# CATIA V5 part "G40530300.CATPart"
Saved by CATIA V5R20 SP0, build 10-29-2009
Part number: G40530300
Revision: 5
Definition: design
Nomenclature: G40530300
Source: made
Description: NOT SPECIFIED
Bounding box of the stored display mesh (mm): x -150 to 150, y -12.5 to 12.5, z -30 to 0
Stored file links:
  C:\Users\Raffaele\Desktop\3D X SITO CF\BOLEX\29-GUIDE STRIP REF 405\G40530300.CATPart
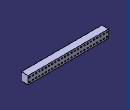
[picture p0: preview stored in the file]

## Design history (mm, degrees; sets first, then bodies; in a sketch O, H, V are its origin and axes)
Body1 "MANIFOLD_SOLID_BREP #7846" (main body)
  Solid1: solid without history
Body2 "MANIFOLD_SOLID_BREP #7984"
  Solid2: solid without history
Body3 "MANIFOLD_SOLID_BREP #8096"
  Solid3: solid without history
Body4 "MANIFOLD_SOLID_BREP #8208"
  Solid4: solid without history
Body5 "MANIFOLD_SOLID_BREP #8320"
  Solid5: solid without history
Body6 "MANIFOLD_SOLID_BREP #8432"
  Solid6: solid without history
Body7 "MANIFOLD_SOLID_BREP #8544"
  Solid7: solid without history
Body8 "MANIFOLD_SOLID_BREP #8656"
  Solid8: solid without history
Body9 "MANIFOLD_SOLID_BREP #8768"
  Solid9: solid without history
Body10 "MANIFOLD_SOLID_BREP #8880"
  Solid10: solid without history
Body11 "MANIFOLD_SOLID_BREP #8992"
  Solid11: solid without history
Body12 "MANIFOLD_SOLID_BREP #9104"
  Solid12: solid without history
Body13 "MANIFOLD_SOLID_BREP #9242"
  Solid13: solid without history
Body14 "MANIFOLD_SOLID_BREP #9380"
  Solid14: solid without history
Body15 "MANIFOLD_SOLID_BREP #9518"
  Solid15: solid without history
Body16 "MANIFOLD_SOLID_BREP #9656"
  Solid16: solid without history
Body17 "MANIFOLD_SOLID_BREP #9794"
  Solid17: solid without history
Body18 "MANIFOLD_SOLID_BREP #9932"
  Solid18: solid without history
Body19 "MANIFOLD_SOLID_BREP #10070"
  Solid19: solid without history
Body20 "MANIFOLD_SOLID_BREP #10208"
  Solid20: solid without history
Body21 "MANIFOLD_SOLID_BREP #10320"
  Solid21: solid without history
Body22 "MANIFOLD_SOLID_BREP #10432"
  Solid22: solid without history
Body23 "MANIFOLD_SOLID_BREP #10544"
  Solid23: solid without history
Body24 "MANIFOLD_SOLID_BREP #10656"
  Solid24: solid without history
Body25 "MANIFOLD_SOLID_BREP #10768"
  Solid25: solid without history
Body26 "MANIFOLD_SOLID_BREP #10880"
  Solid26: solid without history
Body27 "MANIFOLD_SOLID_BREP #10992"
  Solid27: solid without history
Body28 "MANIFOLD_SOLID_BREP #11104"
  Solid28: solid without history
Body29 "MANIFOLD_SOLID_BREP #11216"
  Solid29: solid without history
Body30 "MANIFOLD_SOLID_BREP #11328"
  Solid30: solid without history
Body31 "MANIFOLD_SOLID_BREP #11466"
  Solid31: solid without history
Body32 "MANIFOLD_SOLID_BREP #11604"
  Solid32: solid without history
Body33 "MANIFOLD_SOLID_BREP #11742"
  Solid33: solid without history
Body34 "MANIFOLD_SOLID_BREP #11880"
  Solid34: solid without history
Body35 "MANIFOLD_SOLID_BREP #12018"
  Solid35: solid without history
Body36 "MANIFOLD_SOLID_BREP #12156"
  Solid36: solid without history
Body37 "MANIFOLD_SOLID_BREP #12268"
  Solid37: solid without history
Body38 "MANIFOLD_SOLID_BREP #12380"
  Solid38: solid without history
Body39 "MANIFOLD_SOLID_BREP #12492"
  Solid39: solid without history
Body40 "MANIFOLD_SOLID_BREP #12604"
  Solid40: solid without history
Body41 "MANIFOLD_SOLID_BREP #12716"
  Solid41: solid without history
Body42 "MANIFOLD_SOLID_BREP #12828"
  Solid42: solid without history
Body43 "MANIFOLD_SOLID_BREP #12940"
  Solid43: solid without history
Body44 "MANIFOLD_SOLID_BREP #13052"
  Solid44: solid without history
Body45 "MANIFOLD_SOLID_BREP #13164"
  Solid45: solid without history
Body46 "MANIFOLD_SOLID_BREP #13276"
  Solid46: solid without history
Body47 "MANIFOLD_SOLID_BREP #13388"
  Solid47: solid without history
Body48 "MANIFOLD_SOLID_BREP #13500"
  Solid48: solid without history
Body49 "MANIFOLD_SOLID_BREP #13612"
  Solid49: solid without history
Body50 "MANIFOLD_SOLID_BREP #13724"
  Solid50: solid without history
Body51 "MANIFOLD_SOLID_BREP #13836"
  Solid51: solid without history
Body52 "MANIFOLD_SOLID_BREP #13948"
  Solid52: solid without history
Body53 "MANIFOLD_SOLID_BREP #14060"
  Solid53: solid without history
Body54 "MANIFOLD_SOLID_BREP #14172"
  Solid54: solid without history
Body55 "MANIFOLD_SOLID_BREP #14284"
  Solid55: solid without history
Body56 "MANIFOLD_SOLID_BREP #14396"
  Solid56: solid without history
Body57 "MANIFOLD_SOLID_BREP #14508"
  Solid57: solid without history
Body58 "MANIFOLD_SOLID_BREP #14646"
  Solid58: solid without history
Body59 "MANIFOLD_SOLID_BREP #14784"
  Solid59: solid without history
Body60 "MANIFOLD_SOLID_BREP #14922"
  Solid60: solid without history
Body61 "MANIFOLD_SOLID_BREP #15060"
  Solid61: solid without history
Body62 "MANIFOLD_SOLID_BREP #15198"
  Solid62: solid without history
Body63 "MANIFOLD_SOLID_BREP #15336"
  Solid63: solid without history
Body64 "MANIFOLD_SOLID_BREP #15474"
  Solid64: solid without history
Body65 "MANIFOLD_SOLID_BREP #15612"
  Solid65: solid without history
Body66 "MANIFOLD_SOLID_BREP #15750"
  Solid66: solid without history
Body67 "MANIFOLD_SOLID_BREP #15862"
  Solid67: solid without history
Body68 "MANIFOLD_SOLID_BREP #15974"
  Solid68: solid without history
Body69 "MANIFOLD_SOLID_BREP #16086"
  Solid69: solid without history
Body70 "MANIFOLD_SOLID_BREP #16198"
  Solid70: solid without history
Body71 "MANIFOLD_SOLID_BREP #16310"
  Solid71: solid without history
Body72 "MANIFOLD_SOLID_BREP #16422"
  Solid72: solid without history
Body73 "MANIFOLD_SOLID_BREP #16534"
  Solid73: solid without history
Body74 "MANIFOLD_SOLID_BREP #16646"
  Solid74: solid without history
Body75 "MANIFOLD_SOLID_BREP #16758"
  Solid75: solid without history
